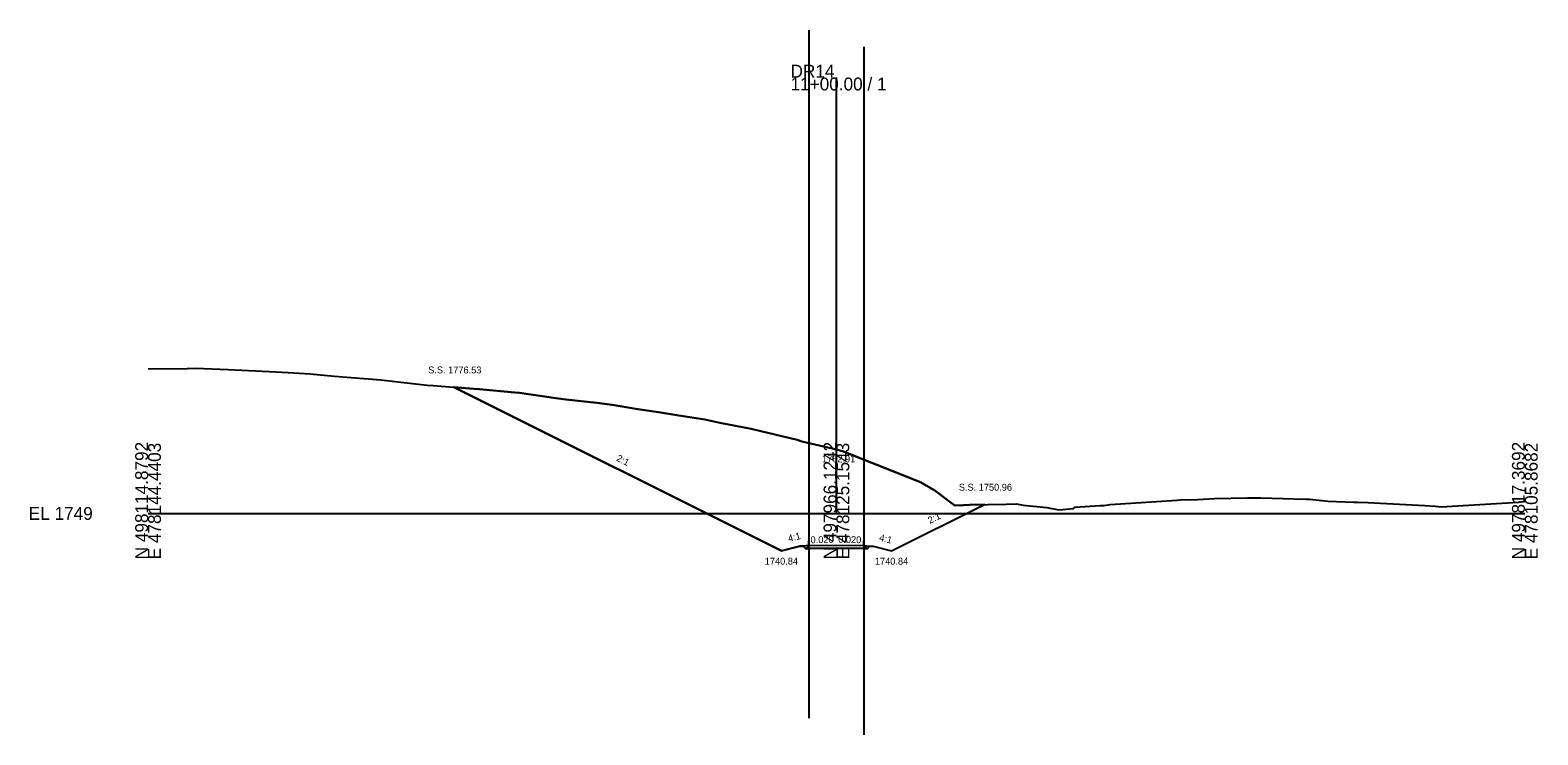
# Model space of a CAD drawing. Extents: x -26 to 303, y -59 to 3067.
# Drawn here: x -25.7 to 302.8, y 951.7 to 1105.3 of the extents above; entities that cross this region are included whole.
import ezdxf

# ---------------------------------------------------------------- set-up
doc = ezdxf.new("R2010")
doc.units = 0
for name, color, linetype in [('Exist Cross Section Cell', 7, 'Continuous'), ('Exist XS Center Line Elevation Label', 7, 'Continuous'), ('Exist XS Ground Line', 7, 'Continuous'), ('Prop XS Ditch Slope Text', 7, 'Continuous'), ('Prop XS Ditch Standard Text', 7, 'Continuous'), ('Prop XS Earthwork Shape', 7, 'Continuous'), ('Prop XS EOT Tick Mark', 7, 'Continuous'), ('Prop XS Finish Grade', 7, 'Continuous'), ('Prop XS Finish Grade Earthwork', 7, 'Continuous'), ('Prop XS Finish Grade Pavement', 7, 'Continuous'), ('Prop XS Pvmt Edge Slope', 7, 'Continuous'), ('Prop XS SE Text', 7, 'Continuous'), ('Prop XS Shoulder Borrow Shape', 7, 'Continuous'), ('Prop XS Side Slope Text', 7, 'Continuous'), ('Prop XS SS Elevation Text', 7, 'Continuous'), ('Prop XS Subgrade Earthwork', 7, 'Continuous'), ('Scratch_Level_6', 7, 'Continuous')]:
    doc.layers.add(name, color=color, linetype=linetype)

msp = doc.modelspace()

# ---------------------------------------------------------------- linework, layer by layer
at = {"layer": 'Exist Cross Section Cell'}
for p, q in [((150, 1000), (150, 1095.01)), ((0, 1000), (150, 1000)), ((150, 1000), (300, 1000))]:
    msp.add_line(p, q, dxfattribs=at)
at = {"layer": 'Exist XS Ground Line'}
msp.add_lwpolyline([(0, 1031.55), (8.52, 1031.63), (10.36, 1031.67), (17.45, 1031.41), (20.44, 1031.27), (26.38, 1030.95), (30.53, 1030.74), (35.31, 1030.42), (40.61, 1029.91), (44.24, 1029.61), (50.7, 1029.1), (53.17, 1028.86), (60.79, 1027.98), (62.09, 1027.9), (71.02, 1027.17), (72.18, 1027.07), (79.95, 1026.36), (80.96, 1026.26), (88.88, 1025.14), (91.04, 1024.86), (97.81, 1024.08), (101.13, 1023.65), (106.73, 1022.73), (111.21, 1022.09), (115.66, 1021.36), (121.3, 1020.45), (124.59, 1019.76), (131.39, 1018.42), (133.52, 1017.93), (141.47, 1016.02), (142.45, 1015.72), (150, 1013.91), (151.56, 1013.53), (152.43, 1013.17), (168.35, 1006.8), (171.43, 1004.97), (175, 1002.28), (175.83, 1001.73), (177.69, 1001.8), (178.97, 1001.9), (187.01, 1002.04), (189.25, 1002.08), (190.68, 1001.82), (195.86, 1001.29), (198.44, 1000.82), (201.67, 1001.09), (202, 1001.4), (206.41, 1001.66), (207.45, 1001.7), (208.25, 1001.73), (209.64, 1001.92), (219.72, 1002.6), (224.19, 1002.91), (224.95, 1002.94), (228.68, 1003.05), (232.41, 1003.26), (239.56, 1003.41), (242.16, 1003.41), (242.5, 1003.4), (249.73, 1003.21), (252.44, 1003.11), (253.15, 1003.1), (257.05, 1002.65), (262.71, 1002.49), (263.61, 1002.43), (265.82, 1002.42), (278.21, 1001.7), (280.45, 1001.56), (281.79, 1001.45), (298.62, 1002.49), (300, 1002.69)], dxfattribs=at)
at = {"layer": 'Prop XS Earthwork Shape'}
msp.add_lwpolyline([(156, 992.33), (156.68, 992.32), (157.26, 992.9), (158, 992.84), (162, 991.84), (182.24, 1001.96), (178.97, 1001.9), (177.69, 1001.8), (175.83, 1001.73), (175, 1002.28), (171.43, 1004.97), (168.35, 1006.8), (152.43, 1013.17), (151.56, 1013.53), (150, 1013.91), (142.45, 1015.72), (141.47, 1016.02), (133.52, 1017.93), (131.39, 1018.42), (124.59, 1019.76), (121.3, 1020.45), (115.66, 1021.36), (111.21, 1022.09), (106.73, 1022.73), (101.13, 1023.65), (97.81, 1024.08), (91.04, 1024.86), (88.88, 1025.14), (80.96, 1026.26), (79.95, 1026.36), (72.18, 1027.07), (71.02, 1027.17), (66.61, 1027.53), (138, 991.84), (142, 992.84), (142.74, 992.9), (143.32, 992.32), (144, 992.33), (150, 992.45)], close=True, dxfattribs=at)
at = {"layer": 'Prop XS EOT Tick Mark'}
for p, q in [((144, 993), (144, 994)), ((156, 993), (156, 994))]:
    msp.add_line(p, q, dxfattribs=at)
at = {"layer": 'Prop XS Finish Grade'}
for p, q in [((144, 993), (142.74, 992.9)), ((156, 993), (157.26, 992.9))]:
    msp.add_line(p, q, dxfattribs=at)
at = {"layer": 'Prop XS Finish Grade Earthwork'}
for p, q in [((138, 991.84), (66.61, 1027.53)), ((162, 991.84), (182.24, 1001.96)), ((142, 992.84), (138, 991.84)), ((142.74, 992.9), (142, 992.84)), ((157.26, 992.9), (158, 992.84)), ((158, 992.84), (162, 991.84))]:
    msp.add_line(p, q, dxfattribs=at)
at = {"layer": 'Prop XS Finish Grade Pavement'}
for p, q in [((144, 993), (150, 993.12)), ((150, 993.12), (156, 993))]:
    msp.add_line(p, q, dxfattribs=at)
at = {"layer": 'Prop XS Pvmt Edge Slope'}
for p, q in [((144, 993), (143.32, 992.32)), ((156, 993), (156.68, 992.32))]:
    msp.add_line(p, q, dxfattribs=at)
at = {"layer": 'Prop XS Shoulder Borrow Shape'}
for p, q in [((144, 993), (142.74, 992.9)), ((142.74, 992.9), (143.32, 992.32)), ((143.32, 992.32), (144, 993)), ((144, 993), (144, 993))]:
    msp.add_line(p, q, dxfattribs=at)
for points in [[(144, 993), (142.74, 992.9), (143.32, 992.32)], [(156, 993), (157.26, 992.9), (156.68, 992.32)]]:
    msp.add_lwpolyline(points, close=True, dxfattribs=at)
at = {"layer": 'Prop XS Subgrade Earthwork'}
for p, q in [((143.32, 992.32), (142.74, 992.9)), ((144, 992.33), (143.32, 992.32)), ((150, 992.45), (144, 992.33)), ((156, 992.33), (150, 992.45)), ((156, 992.33), (156.68, 992.32)), ((156.68, 992.32), (157.26, 992.9))]:
    msp.add_line(p, q, dxfattribs=at)
at = {"layer": 'Scratch_Level_6'}
for p, q in [((144, 1105.35), (144, 955.35)), ((156, 1101.74), (156, 951.74))]:
    msp.add_line(p, q, dxfattribs=at)

# ---------------------------------------------------------------- texts
at = {"layer": 'Exist Cross Section Cell'}
for s, p in [('DR14', (140, 1095.01)), ('11+00.00 / 1', (140, 1092.21)), ('EL 1749', (-26, 998.6))]:
    msp.add_text(s, height=2.8, dxfattribs=at).set_placement(p)
for s, p in [('N 498114.8792', (0, 990)), ('E 478144.4403', (2.8, 990)), ('N 497966.1242', (150, 990)), ('E 478125.1543', (152.8, 990)), ('N 497817.3692', (300, 990)), ('E 478105.8682', (302.8, 990))]:
    msp.add_text(s, height=2.8, rotation=90, dxfattribs=at).set_placement(p)
at = {"layer": 'Exist XS Center Line Elevation Label'}
msp.add_text('1762.91', height=1.5, dxfattribs=at).set_placement((146.86, 1011.16))
at = {"layer": 'Prop XS Ditch Slope Text'}
for rotation, p in [(14.0362, (139.64, 993.79)), (345.9638, (159.21, 994.08))]:
    msp.add_text('4:1', height=1.5, rotation=rotation, dxfattribs=at).set_placement(p)
at = {"layer": 'Prop XS Ditch Standard Text'}
for p in [(134.38, 988.84), (158.38, 988.84)]:
    msp.add_text('1740.84', height=1.5, dxfattribs=at).set_placement(p)
at = {"layer": 'Prop XS SE Text'}
for rotation, p in [(1.1458, (144.38, 993.5)), (358.8542, (150.38, 993.61))]:
    msp.add_text('0.020', height=1.5, rotation=rotation, dxfattribs=at).set_placement(p)
at = {"layer": 'Prop XS Side Slope Text'}
for rotation, p in [(333.4349, (101.91, 1011.56)), (26.5651, (170.39, 997.71))]:
    msp.add_text('2:1', height=1.5, rotation=rotation, dxfattribs=at).set_placement(p)
at = {"layer": 'Prop XS SS Elevation Text'}
for s, p in [('S.S. 1776.53', (61.04, 1030.53)), ('S.S. 1750.96', (176.66, 1004.96))]:
    msp.add_text(s, height=1.5, dxfattribs=at).set_placement(p)

doc.saveas('drawing.dxf')
